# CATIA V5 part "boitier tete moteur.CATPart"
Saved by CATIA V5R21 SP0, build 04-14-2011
Part number: boitier tete moteur
Material "Aluminium": density 2710 kg/m3, Young's modulus 7e+10 Pa, Poisson ratio 0.346, thermal expansion 2.36e-05 1/K
Bounding box of the stored display mesh (mm): x -15.717 to 15.717, y 0 to 14, z -15.717 to 15.717
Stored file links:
  C:\Users\Olivier\Desktop\redaction CATIA (local)\CATIA\DONNEES\Exercice mise en plan 2 (Pompe de ventilation)\Pompe de ventilation (Product inclus)\boitier tete moteur.CATPart
  C:\Program Files\Dassault Systemes\B21\win_b64\startup\materials\French\Catalog.CATMaterial
  C:\Users\Olivier\Desktop\redaction CATIA (local)\CATIA\DONNEES\Exercice mise en plan 2 (Pompe de ventilation)\Pompe de ventilation (Product inclus)\CATIA_EnvironmentMap_DSBlack_512x512.jpg
  C:\Users\Olivier\Desktop\redaction CATIA (local)\pompe à moteur de ventilation refait\Pompe_a_moteur_de_ventilation.CATProduct
  C:\Users\Olivier\Desktop\redaction CATIA (local)\pompe à moteur de ventilation refait\Ecrou a collerette M5.CATPart
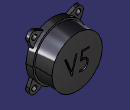
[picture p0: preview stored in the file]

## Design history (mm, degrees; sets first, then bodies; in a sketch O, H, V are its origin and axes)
Body1 (main body), material "Aluminium"
  Sketch1 on zx-plane, origin (0, 0, 0), H (-1, 0, 0), V (0, 0, 1)
    circle A1 centre (0, 0) radius 15.5
    circle A2 centre (0, 0) radius 14.5
    radius A2 = 14.5
  MultiPad1: profile Sketch1, domains (length 14; length 4)
  Sketch2 on face of MultiPad1, origin (0, 0, 0), H (1, 0, 0), V (0, 0, 1)
    circle A1 centre (0, 0) radius 11.5
  Pocket1: profile Sketch2, direction (0, 1, 0), length 12
  Sketch3 on face of MultiPad1, origin (0, 0, 0), H (1, 0, 0), V (0, 0, 1)
    projected circle E1 centre (0, 0) radius 15.5 from edge [face of MultiPad1 | face of MultiPad1 from Sketch1.A1]
    projected arc E2 centre (0, 0) radius 15.5 from (-7.465, 13.5839) to (-13.5839, 7.465) ccw from edge [face of MultiPad1 | face of MultiPad1 from Sketch1.A1]
    projected arc E3 centre (0, 0) radius 15.5 from (-13.5839, -7.465) to (-7.465, -13.5839) ccw from edge [face of MultiPad1 | face of MultiPad1 from Sketch1.A1]
    projected arc E4 centre (0, 0) radius 15.5 from (7.465, -13.5839) to (13.5839, -7.465) ccw from edge [face of MultiPad1 | face of MultiPad1 from Sketch1.A1]
    projected arc E5 centre (0, 0) radius 15.5 from (13.5839, 7.465) to (7.465, 13.5839) ccw from edge [face of MultiPad1 | face of MultiPad1 from Sketch1.A1]
    circle A1 centre (12.7279, 12.7279) radius 1.5
    point P1 (12.7279, 12.7279)
    arc A2 centre (12.7279, 12.7279) radius 3 from (15.4468, 11.4601) to (11.4601, 15.4468) ccw
    line L1 (15.4468, 11.4601) -> (13.5839, 7.465)
    point P2 (15.4468, 11.4601)
    point P3 (11.4601, 15.4468)
    line L2 (11.4601, 15.4468) -> (7.465, 13.5839)
    point P4 (7.465, 13.5839)
    point P5 (13.5839, 7.465)
    point P7 (-15.4468, 11.4601)
    point P8 (-11.4601, 15.4468)
    point P9 (-7.465, 13.5839)
    point P10 (-13.5839, 7.465)
    circle A3 centre (-12.7279, 12.7279) radius 1.5
    arc A4 centre (-12.7279, 12.7279) radius 3 from (-15.4468, 11.4601) to (-11.4601, 15.4468) cw
    line L3 (-15.4468, 11.4601) -> (-13.5839, 7.465)
    line L4 (-11.4601, 15.4468) -> (-7.465, 13.5839)
    point P12 (15.4468, -11.4601)
    point P13 (11.4601, -15.4468)
    point P14 (7.465, -13.5839)
    point P15 (13.5839, -7.465)
    point P17 (-15.4468, -11.4601)
    point P18 (-11.4601, -15.4468)
    point P19 (-7.465, -13.5839)
    point P20 (-13.5839, -7.465)
    circle A5 centre (12.7279, -12.7279) radius 1.5
    arc A6 centre (12.7279, -12.7279) radius 3 from (15.4468, -11.4601) to (11.4601, -15.4468) cw
    line L5 (15.4468, -11.4601) -> (13.5839, -7.465)
    line L6 (11.4601, -15.4468) -> (7.465, -13.5839)
    circle A7 centre (-12.7279, -12.7279) radius 1.5
    arc A8 centre (-12.7279, -12.7279) radius 3 from (-15.4468, -11.4601) to (-11.4601, -15.4468) ccw
    line L7 (-15.4468, -11.4601) -> (-13.5839, -7.465)
    line L8 (-11.4601, -15.4468) -> (-7.465, -13.5839)
    distance P1 O = 18
    radius A2 = 3
    tangency: A2 L1
    coincidence: E1 P4, E1 P5
    symmetry: P2 P7 V, P3 P8 V, P4 P9 V, P5 P10 V, A1 A3 V, A2 A4 V, L1 L3 V, L2 L4 V, P2 P12 H, P3 P13 H, P4 P14 H, P5 P15 H, P7 P17 H, P8 P18 H, P9 P19 H, P10 P20 H, A1 A5 H, A2 A6 H, L1 L5 H, L2 L6 H, A3 A7 H, A4 A8 H, L3 L7 H, L4 L8 H
  Pad1: profile Sketch3, direction (0, 1, 0), length 2
  Sketch4 on face of MultiPad1, origin (0, 14, 0), H (-1, 0, 0), V (0, 0, 1)
    line L1 (-7.2074, 4.3533) -> (-3.0577, -5.6747)
    point P2 (-3.0577, -5.6747)
    point P3 (-3.0577, -5.6747)
    point P4 (0.0056, 4.3533)
    line L2 (0.0056, 4.3533) -> (-3.0577, -5.6747)
    line L3 (-7.2074, 4.3533) -> (-6.1898, 4.3533)
    line L4 (-6.1898, 4.3533) -> (-3.0677, -3.1914)
    line L5 (-3.0677, -3.1914) -> (-0.7629, 4.3533)
    point P7 (-0.7629, 4.3533)
    line L6 (-0.7629, 4.3533) -> (0.0056, 4.3533)
    point P8 (0.0056, 4.3533)
    point P9 (2.7205, 4.3533)
    line L7 (2.7205, 4.3533) -> (2.0273, -0.6137)
    line L8 (2.7205, 4.3533) -> (7.0034, 4.3533)
    line L9 (7.0034, 4.3533) -> (6.8938, 3.5681)
    line L10 (6.8938, 3.5681) -> (3.3501, 3.5681)
    line L11 (3.3501, 3.5681) -> (2.8903, 0.2738)
    point P14 (2.8903, 0.2738)
    spline S1 through (2.8903, 0.2738) (6.1305, -1.2523) (5.8312, -4.3043) (1.3117, -5.7405)
    offsetcurve C1
    construction line L12 (2.8903, 0.2738) -> (2.9402, -0.6249)
    point P17 (2.8903, 0.2738)
    construction line L13 through (2.8903, 0.2738) direction (-0.9985, -0.0554)
    construction line L14 (1.3117, -5.7405) -> (1.5746, -4.8798)
    point P18 (1.3117, -5.7405)
    construction line L15 through (1.1611, -5.6945) direction (-0.9564, 0.2922)
    line L16 (2.9402, -0.6249) -> (2.0273, -0.6137)
    line L17 (1.5746, -4.8798) -> (1.3117, -5.7405)
    point P19 (1.3117, -5.7405)
    point P20 (2.8903, 0.2738)
    point P21 (1.3117, -5.7405)
    horizontal: L3 H, L6 H, L8 H, L10 H
    parallelism: L4 L1, L5 L2, L9 L7, L11 L7, L17 L2
    coincidence: P7 L3, P8 L2, P9 L6, P20 P14, P21 L7, P20 P17, P21 P18, P4 P8, P19 P21, P2 P3
    tangency: L13 S1, L15 S1
    perpendicularity: L12 L13, L14 L15
  Pocket2: profile Sketch4, direction (0, -1, 0), length 1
